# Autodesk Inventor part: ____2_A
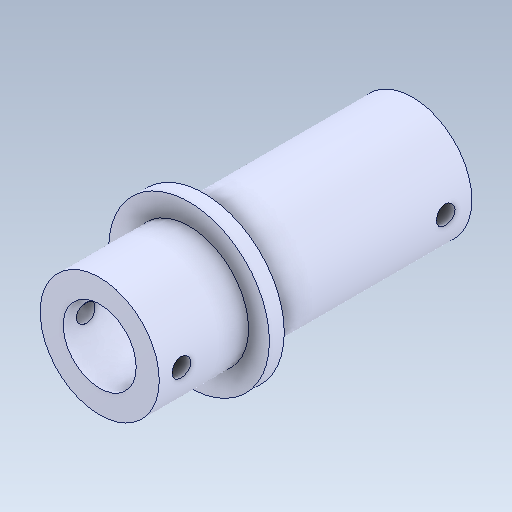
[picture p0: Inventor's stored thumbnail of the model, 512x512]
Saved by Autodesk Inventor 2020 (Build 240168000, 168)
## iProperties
Created: 2017-09
Part Number: ____2_A
Material: Générique
Document SubType Name: Modeling
Designer: bruno
Density: 1 g/cm^3
Appearance: Par défaut
Mass: 5.54585 g
Surface Area: 40.8105 cm^2
Volume: 5.54585 cm^3
Sending System: SolidWorks 2016
Author: bruno
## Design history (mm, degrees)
feature "Importée1"
node "Solide1"
